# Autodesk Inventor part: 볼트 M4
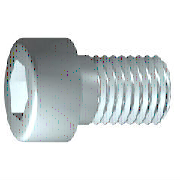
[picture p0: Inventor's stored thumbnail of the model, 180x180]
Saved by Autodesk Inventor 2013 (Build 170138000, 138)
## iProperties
IsCustomPart: 0
Created: 2016-04
Part Number: 볼트 M4
Material: 강철, 연강
Description: 6각머리 태핑 나사
Document SubType Name: Modeling
Standard: KS B 1003
Designer: mdu
Standards Organization: KS
Language: ko-KR
Size Designation: M 4 x 10
Categories: <MemberInstance><Categories><Category DisplayName="조임쇠" InternalName="e4da775c-781d-43d5-af7c-5136215cf5a6" Mnemonic="FSTN"><Category DisplayName="볼트" InternalN
Density: 7.86 g/cm^3
Mass: 2.0371 g
Surface Area: 3.0572 cm^2
Volume: 0.259174 cm^3
Author: mdu
Revision Number: 1
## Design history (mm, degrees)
sketch "스케치1"
  geometry: L1 (-1, 0)-(10, 0); L2 (10, 0)-(10, 2); L3 (10, 2)-(1.75, 2); L4 (1.75, 2)-(1.32, 2); L5 (1.32, 2)-(0, 2); L6 (0, 2)-(0, 3.5); L7 (0, 3.5)-(-4, 3.5); L8 (-4, 3.5)-(-4, 1.732); L9 (-4, 1.732)-(-2, 1.732); L10 (-2, 1.732)-(-1, 0); L11 (-6.8, 0)-(12.8, 0) reference; L12 (0, -0.7)-(0, 4.2) reference; L13 (1.75, 2)-(0, 2)
  constraints: 22 end point, 6 parallel, 2 collinear, 2 perpendicular, 1 horizontal, 1 point on line
  dimensions: "d1" = 8.25 distance from line of L3.end L2 (= GEL); "d2" = 0.42952 distance of L4.end L3.end (computed from GAL); "d3" = 4 distance between parallel lines of L8 L6 (= KOH); "d4" = 2 distance of L8.end L9.end (= INTI); "d5" = 60 deg angle of L10 L1; "d6" = 4 diameter of L3 L1 (= GD); "d7" = 4 diameter of L5 L1 (= BDM); "d8" = 3.4641 diameter of L9 L1 (= 1.1547 x SW); "d9" = 7 diameter of L7 L1 (= KOD); "d26" = 10 distance between parallel lines of L12 L2 (= NLG)
revolve "본체" sketch "스케치1" stored, may be unused: angle "d10" = 90 deg
sketch "스케치2"
  geometry: L1 (0, -4.9)-(0, 4.9) reference; L2 (-4.9, 0)-(4.9, 0) reference; L3 (1.732, 0)-(0.866, -1.5); L4 (0.866, -1.5)-(-0.866, -1.5); L5 (-0.866, -1.5)-(-1.732, 0); L6 (-1.732, 0)-(-0.866, 1.5); L7 (-0.866, 1.5)-(0.866, 1.5); L8 (0.866, 1.5)-(1.732, 0); 2 further points
  constraints: 12 end point, 1 coincident, 1 horizontal alignment, 1 point on line, 12 other
extrude "슬롯" join sketch "스케치2" stored distance "d11" = 10; taper "d12" = 0 deg
workplane "Work Plane1"
fillet "Fillet2" dims "d30" = 0.1 (= R)
body "Solid1"
fillet "모깎기1" dims "d17" = 0.4 (= RR)
feature "스레드" dims "d13" = 8.25 (= GEL), "d14" = 0
chamfer "모따기1" distance "d15" = 0.42941 (= -0.5 x SPD + 0.5 x GD); stored, may be unused: second distance "d16" = 0.42941 (= GUL), angle "d27" = 45 deg
other parameters: "GD" = 4 (= NND) [user parameter; used in 2 equation terms], "NLG" = 10 [user parameter; used in 1 equation term], "GEL" = 8.25 [user parameter; used in 2 equation terms], "KOD" = 7 [user parameter; used in 1 equation term], "KOH" = 4 [user parameter; used in 1 equation term], "INTI" = 2 [user parameter; used in 1 equation term], "GAL" = 0.42941 (= 0.61345 x PTC) [user parameter; used in 1 equation term], "GUL" = 0.42941 (= 0.61345 x PTC) [user parameter; used in 1 equation term], "BDM" = 4 (= NND) [user parameter; used in 1 equation term], "SW" = 3 [user parameter; used in 2 equation terms], "RR" = 0.4 [user parameter; used in 1 equation term], "SPD" = 3.14117 (= NND - 1.2269 x PTC) [user parameter; used in 1 equation term], "d19" = 0, "d28" = 0, "d29" = 0, "R" = 0.1 [user parameter; used in 1 equation term], "PHH" = 0.2 [user parameter], "GD1" = 3.14117 (= THREADDIA - 1.2269 x PTC) [user parameter], "THREADDIA" = 4 [user parameter; used in 1 equation term], "FAWI" = 45 deg [user parameter], "TPU" = 14.28571 (computed from PTC) [user parameter], "PTC" = 0.7 [user parameter; used in 5 equation terms], "NND" = 4 [user parameter; used in 3 equation terms], "TOA" = 30 deg [user parameter], "E0" = 3.465 (= 1.155 x SW) [user parameter]
